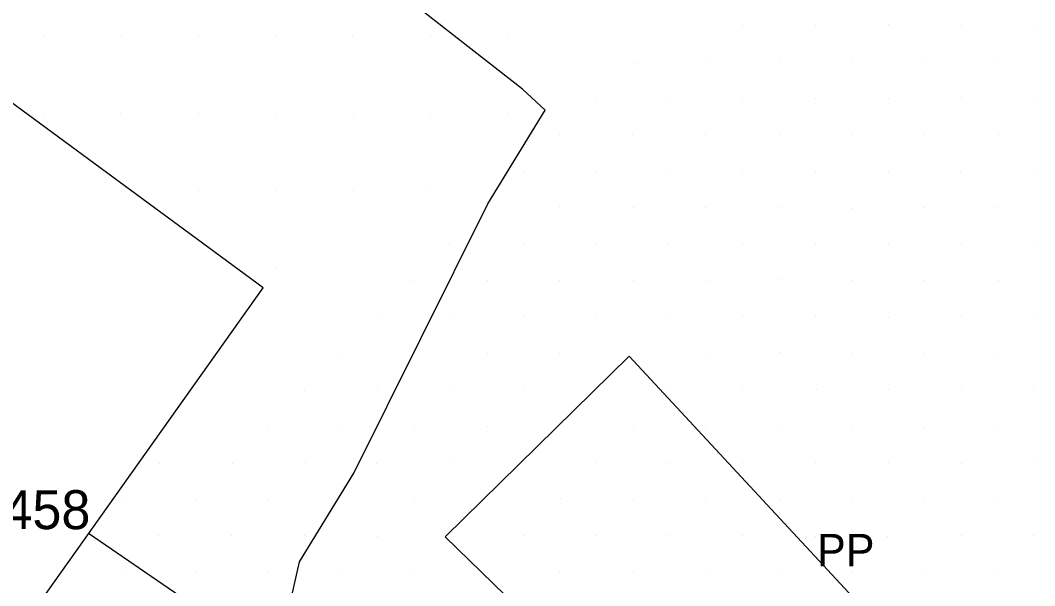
# Model space of a CAD drawing. Extents: x 1602514 to 1609837, y 863887 to 871157.
# Drawn here: x 1605194.3 to 1605391, y 866946.5 to 867056.2 of the extents above; entities that cross this region are included whole.
import ezdxf

# ---------------------------------------------------------------- set-up
doc = ezdxf.new("R2010")
doc.units = 0
for name, color, linetype in [('Survey-Buildings', 7, 'Continuous'), ('Survey-Edge of pavement', 7, 'Continuous'), ('Survey-Entrances', 7, 'Continuous'), ('Survey-Fences', 7, 'Continuous'), ('Survey-Spot dirt', 7, 'Continuous'), ('Survey-Text-Elevation', 7, 'Continuous'), ('Utility-Pole', 7, 'Continuous')]:
    doc.layers.add(name, color=color, linetype=linetype)

msp = doc.modelspace()

# ---------------------------------------------------------------- linework, layer by layer
at = {"layer": 'Survey-Buildings'}
msp.add_lwpolyline([(1605190.06, 866932.05), (1605241.42, 867004.29), (1605170.03, 867056.81), (1605155.81, 867037.05), (1605154.06, 867034.61), (1605138.78, 867044.23), (1605166.94, 867086.69), (1605169.84, 867084.69), (1605184.21, 867105.16), (1605132.01, 867142.68), (1605116.66, 867120.43), (1605129.33, 867112.32), (1605120.65, 867099.05), (1605101.98, 867070.67), (1605103.93, 867068.47), (1605097.48, 867060.65), (1605146.75, 867024.45), (1605117.85, 866984.27), (1605136.88, 866970.51)], dxfattribs=at)
msp.add_lwpolyline([(1605190.06, 866932.05), (1605241.42, 867004.29), (1605170.03, 867056.81), (1605155.81, 867037.05), (1605154.06, 867034.61), (1605138.78, 867044.23), (1605166.94, 867086.69), (1605169.84, 867084.69), (1605184.21, 867105.16), (1605132.01, 867142.68), (1605116.66, 867120.43), (1605129.33, 867112.32), (1605120.65, 867099.05), (1605101.98, 867070.67), (1605103.93, 867068.47), (1605097.48, 867060.65), (1605146.75, 867024.45), (1605117.85, 866984.27), (1605136.88, 866970.51)], dxfattribs=at)
at = {"layer": 'Survey-Edge of pavement'}
msp.add_lwpolyline([(1605073.3, 866946.51), (1605034.83, 866891.76), (1605147.19, 866811.71), (1605195.19, 866879.11), (1605236.38, 866936.87), (1605207.52, 866956.61)], dxfattribs=at)
msp.add_lwpolyline([(1605073.3, 866946.51), (1605034.83, 866891.76), (1605147.19, 866811.71), (1605195.19, 866879.11), (1605236.38, 866936.87), (1605207.52, 866956.61)], dxfattribs=at)
at = {"layer": 'Survey-Entrances'}
for points in [[(1605291.69, 867042.8), (1605245.98, 867078.59), (1605219.04, 867104.4), (1605203.54, 867111.71), (1605201.31, 867118.34)], [(1605291.69, 867042.8), (1605245.98, 867078.59), (1605219.04, 867104.4), (1605203.54, 867111.71), (1605201.31, 867118.34)], [(1605244.46, 866933.37), (1605248.44, 866951.15), (1605258.96, 866968.37), (1605284.98, 867020.57), (1605296.07, 867038.78), (1605291.69, 867042.8)], [(1605244.46, 866933.37), (1605248.44, 866951.15), (1605258.96, 866968.37), (1605284.98, 867020.57), (1605296.07, 867038.78), (1605291.69, 867042.8)]]:
    msp.add_lwpolyline(points, dxfattribs=at)
at = {"layer": 'Survey-Fences'}
msp.add_lwpolyline([(1605276.69, 866955.98), (1605312.32, 866991.05), (1605363.36, 866936.1), (1605330.31, 866903.81)], close=True, dxfattribs=at)
msp.add_lwpolyline([(1605276.69, 866955.98), (1605312.32, 866991.05), (1605363.36, 866936.1), (1605330.31, 866903.81)], close=True, dxfattribs=at)
at = {"layer": 'Survey-Spot dirt'}
for p, q in [((1605362.66, 867055.34), (1605362.66, 867055.34)), ((1605362.66, 867055.34), (1605362.66, 867055.34)), ((1605334.23, 867055.22), (1605334.23, 867055.22)), ((1605334.23, 867055.22), (1605334.23, 867055.22)), ((1605348.41, 867055.12), (1605348.41, 867055.12)), ((1605348.41, 867055.12), (1605348.41, 867055.12)), ((1605376.74, 867055.15), (1605376.74, 867055.15)), ((1605376.74, 867055.15), (1605376.74, 867055.15)), ((1605390.85, 867055.23), (1605390.85, 867055.23)), ((1605390.85, 867055.23), (1605390.85, 867055.23)), ((1605198.88, 867053.12), (1605198.88, 867053.12)), ((1605198.88, 867053.12), (1605198.88, 867053.12)), ((1605213.9, 867053.06), (1605213.9, 867053.06)), ((1605213.9, 867053.06), (1605213.9, 867053.06)), ((1605228.95, 867053.03), (1605228.95, 867053.03)), ((1605228.95, 867053.03), (1605228.95, 867053.03)), ((1605243.8, 867053.08), (1605243.8, 867053.08)), ((1605243.8, 867053.08), (1605243.8, 867053.08)), ((1605258.8, 867053.03), (1605258.8, 867053.03)), ((1605258.8, 867053.03), (1605258.8, 867053.03)), ((1605273.88, 867053.03), (1605273.88, 867053.03)), ((1605273.88, 867053.03), (1605273.88, 867053.03)), ((1605288.98, 867052.83), (1605288.98, 867052.83)), ((1605288.98, 867052.83), (1605288.98, 867052.83)), ((1605313.3, 867047.8), (1605313.3, 867047.8)), ((1605313.3, 867047.8), (1605313.3, 867047.8)), ((1605327.26, 867048.04), (1605327.26, 867048.04)), ((1605327.26, 867048.04), (1605327.26, 867048.04)), ((1605341.43, 867048.16), (1605341.43, 867048.16)), ((1605341.43, 867048.16), (1605341.43, 867048.16)), ((1605355.55, 867048.12), (1605355.55, 867048.12)), ((1605355.55, 867048.12), (1605355.55, 867048.12)), ((1605369.74, 867048.04), (1605369.74, 867048.04)), ((1605369.74, 867048.04), (1605369.74, 867048.04)), ((1605383.81, 867048.19), (1605383.81, 867048.19)), ((1605383.81, 867048.19), (1605383.81, 867048.19)), ((1605306.04, 867041.1), (1605306.04, 867041.1)), ((1605306.04, 867041.1), (1605306.04, 867041.1)), ((1605320.17, 867041.04), (1605320.17, 867041.04)), ((1605320.17, 867041.04), (1605320.17, 867041.04)), ((1605334.28, 867040.99), (1605334.28, 867040.99)), ((1605334.28, 867040.99), (1605334.28, 867040.99)), ((1605348.38, 867041.04), (1605348.38, 867041.04)), ((1605348.38, 867041.04), (1605348.38, 867041.04)), ((1605362.64, 867041.07), (1605362.64, 867041.07)), ((1605362.64, 867041.07), (1605362.64, 867041.07)), ((1605376.73, 867041.14), (1605376.73, 867041.14)), ((1605376.73, 867041.14), (1605376.73, 867041.14)), ((1605390.95, 867040.91), (1605390.95, 867040.91)), ((1605390.95, 867040.91), (1605390.95, 867040.91)), ((1605199.02, 867037.9), (1605199.02, 867037.9)), ((1605199.02, 867037.9), (1605199.02, 867037.9)), ((1605213.79, 867038.08), (1605213.79, 867038.08)), ((1605213.79, 867038.08), (1605213.79, 867038.08)), ((1605228.86, 867038.07), (1605228.86, 867038.07)), ((1605228.86, 867038.07), (1605228.86, 867038.07)), ((1605243.89, 867038), (1605243.89, 867038)), ((1605243.89, 867038), (1605243.89, 867038)), ((1605258.93, 867037.97), (1605258.93, 867037.97)), ((1605258.93, 867037.97), (1605258.93, 867037.97)), ((1605273.9, 867037.99), (1605273.9, 867037.99)), ((1605273.9, 867037.99), (1605273.9, 867037.99)), ((1605288.84, 867038.05), (1605288.84, 867038.05)), ((1605288.84, 867038.05), (1605288.84, 867038.05)), ((1605298.84, 867033.98), (1605298.84, 867033.98)), ((1605298.84, 867033.98), (1605298.84, 867033.98)), ((1605312.99, 867034.05), (1605312.99, 867034.05)), ((1605312.99, 867034.05), (1605312.99, 867034.05)), ((1605327.18, 867033.98), (1605327.18, 867033.98)), ((1605327.18, 867033.98), (1605327.18, 867033.98)), ((1605341.43, 867034.06), (1605341.43, 867034.06)), ((1605341.43, 867034.06), (1605341.43, 867034.06)), ((1605355.58, 867033.99), (1605355.58, 867033.99)), ((1605355.58, 867033.99), (1605355.58, 867033.99)), ((1605369.67, 867033.97), (1605369.67, 867033.97)), ((1605369.67, 867033.97), (1605369.67, 867033.97)), ((1605383.86, 867034.06), (1605383.86, 867034.06)), ((1605383.86, 867034.06), (1605383.86, 867034.06)), ((1605291.89, 867026.86), (1605291.89, 867026.86)), ((1605291.89, 867026.86), (1605291.89, 867026.86)), ((1605305.92, 867026.89), (1605305.92, 867026.89)), ((1605305.92, 867026.89), (1605305.92, 867026.89)), ((1605320.18, 867026.81), (1605320.18, 867026.81)), ((1605320.18, 867026.81), (1605320.18, 867026.81)), ((1605334.36, 867026.97), (1605334.36, 867026.97)), ((1605334.36, 867026.97), (1605334.36, 867026.97)), ((1605348.51, 867026.93), (1605348.51, 867026.93)), ((1605348.51, 867026.93), (1605348.51, 867026.93)), ((1605362.65, 867026.86), (1605362.65, 867026.86)), ((1605362.65, 867026.86), (1605362.65, 867026.86)), ((1605376.65, 867026.89), (1605376.65, 867026.89)), ((1605376.65, 867026.89), (1605376.65, 867026.89)), ((1605390.88, 867026.87), (1605390.88, 867026.87)), ((1605390.88, 867026.87), (1605390.88, 867026.87)), ((1605214, 867023.17), (1605214, 867023.17)), ((1605214, 867023.17), (1605214, 867023.17)), ((1605228.94, 867023.1), (1605228.94, 867023.1)), ((1605228.94, 867023.1), (1605228.94, 867023.1)), ((1605243.78, 867023.08), (1605243.78, 867023.08)), ((1605243.78, 867023.08), (1605243.78, 867023.08)), ((1605259, 867023.11), (1605259, 867023.11)), ((1605259, 867023.11), (1605259, 867023.11)), ((1605273.66, 867023.15), (1605273.66, 867023.15)), ((1605273.66, 867023.15), (1605273.66, 867023.15)), ((1605298.82, 867020.05), (1605298.82, 867020.05)), ((1605298.82, 867020.05), (1605298.82, 867020.05)), ((1605313.19, 867019.85), (1605313.19, 867019.85)), ((1605313.19, 867019.85), (1605313.19, 867019.85)), ((1605327.22, 867019.94), (1605327.22, 867019.94)), ((1605327.22, 867019.94), (1605327.22, 867019.94)), ((1605341.3, 867019.84), (1605341.3, 867019.84)), ((1605341.3, 867019.84), (1605341.3, 867019.84)), ((1605369.62, 867019.87), (1605369.62, 867019.87)), ((1605369.62, 867019.87), (1605369.62, 867019.87)), ((1605383.73, 867019.87), (1605383.73, 867019.87)), ((1605383.73, 867019.87), (1605383.73, 867019.87)), ((1605355.46, 867019.75), (1605355.46, 867019.75)), ((1605355.46, 867019.75), (1605355.46, 867019.75)), ((1605277.61, 867012.75), (1605277.61, 867012.75)), ((1605277.61, 867012.75), (1605277.61, 867012.75)), ((1605291.93, 867012.74), (1605291.93, 867012.74)), ((1605291.93, 867012.74), (1605291.93, 867012.74)), ((1605306.04, 867012.84), (1605306.04, 867012.84)), ((1605306.04, 867012.84), (1605306.04, 867012.84)), ((1605320.01, 867012.81), (1605320.01, 867012.81)), ((1605320.01, 867012.81), (1605320.01, 867012.81)), ((1605334.3, 867012.77), (1605334.3, 867012.77)), ((1605334.3, 867012.77), (1605334.3, 867012.77)), ((1605348.57, 867012.77), (1605348.57, 867012.77)), ((1605348.57, 867012.77), (1605348.57, 867012.77)), ((1605362.62, 867012.81), (1605362.62, 867012.81)), ((1605362.62, 867012.81), (1605362.62, 867012.81)), ((1605376.7, 867012.83), (1605376.7, 867012.83)), ((1605376.7, 867012.83), (1605376.7, 867012.83)), ((1605390.97, 867012.76), (1605390.97, 867012.76)), ((1605390.97, 867012.76), (1605390.97, 867012.76)), ((1605243.86, 867008.03), (1605243.86, 867008.03)), ((1605243.86, 867008.03), (1605243.86, 867008.03)), ((1605270.58, 867005.74), (1605270.58, 867005.74)), ((1605270.58, 867005.74), (1605270.58, 867005.74)), ((1605284.85, 867005.73), (1605284.85, 867005.73)), ((1605284.85, 867005.73), (1605284.85, 867005.73)), ((1605298.9, 867005.69), (1605298.9, 867005.69)), ((1605298.9, 867005.69), (1605298.9, 867005.69)), ((1605313.19, 867005.66), (1605313.19, 867005.66)), ((1605313.19, 867005.66), (1605313.19, 867005.66)), ((1605327.34, 867005.7), (1605327.34, 867005.7)), ((1605327.34, 867005.7), (1605327.34, 867005.7)), ((1605341.23, 867005.86), (1605341.23, 867005.86)), ((1605341.23, 867005.86), (1605341.23, 867005.86)), ((1605355.49, 867005.75), (1605355.49, 867005.75)), ((1605355.49, 867005.75), (1605355.49, 867005.75)), ((1605369.58, 867005.74), (1605369.58, 867005.74)), ((1605369.58, 867005.74), (1605369.58, 867005.74)), ((1605383.88, 867005.63), (1605383.88, 867005.63)), ((1605383.88, 867005.63), (1605383.88, 867005.63)), ((1605263.71, 866998.6), (1605263.71, 866998.6)), ((1605263.71, 866998.6), (1605263.71, 866998.6)), ((1605277.7, 866998.53), (1605277.7, 866998.53)), ((1605277.7, 866998.53), (1605277.7, 866998.53)), ((1605291.8, 866998.67), (1605291.8, 866998.67)), ((1605291.8, 866998.67), (1605291.8, 866998.67)), ((1605305.92, 866998.61), (1605305.92, 866998.61)), ((1605305.92, 866998.61), (1605305.92, 866998.61)), ((1605320.22, 866998.63), (1605320.22, 866998.63)), ((1605320.22, 866998.63), (1605320.22, 866998.63)), ((1605334.26, 866998.78), (1605334.26, 866998.78)), ((1605334.26, 866998.78), (1605334.26, 866998.78)), ((1605348.55, 866998.69), (1605348.55, 866998.69)), ((1605348.55, 866998.69), (1605348.55, 866998.69)), ((1605362.69, 866998.58), (1605362.69, 866998.58)), ((1605362.69, 866998.58), (1605362.69, 866998.58)), ((1605376.76, 866998.67), (1605376.76, 866998.67)), ((1605376.76, 866998.67), (1605376.76, 866998.67)), ((1605390.89, 866998.48), (1605390.89, 866998.48)), ((1605390.89, 866998.48), (1605390.89, 866998.48)), ((1605256.53, 866991.54), (1605256.53, 866991.54)), ((1605256.53, 866991.54), (1605256.53, 866991.54)), ((1605270.63, 866991.61), (1605270.63, 866991.61)), ((1605270.63, 866991.61), (1605270.63, 866991.61)), ((1605284.85, 866991.65), (1605284.85, 866991.65)), ((1605284.85, 866991.65), (1605284.85, 866991.65)), ((1605298.89, 866991.49), (1605298.89, 866991.49)), ((1605298.89, 866991.49), (1605298.89, 866991.49)), ((1605327.3, 866991.46), (1605327.3, 866991.46)), ((1605327.3, 866991.46), (1605327.3, 866991.46)), ((1605341.41, 866991.69), (1605341.41, 866991.69)), ((1605341.41, 866991.69), (1605341.41, 866991.69)), ((1605355.59, 866991.54), (1605355.59, 866991.54)), ((1605355.59, 866991.54), (1605355.59, 866991.54)), ((1605369.61, 866991.56), (1605369.61, 866991.56)), ((1605369.61, 866991.56), (1605369.61, 866991.56)), ((1605383.79, 866991.57), (1605383.79, 866991.57)), ((1605383.79, 866991.57), (1605383.79, 866991.57)), ((1605249.5, 866984.45), (1605249.5, 866984.45)), ((1605249.5, 866984.45), (1605249.5, 866984.45)), ((1605263.62, 866984.57), (1605263.62, 866984.57)), ((1605263.62, 866984.57), (1605263.62, 866984.57)), ((1605277.65, 866984.53), (1605277.65, 866984.53)), ((1605277.65, 866984.53), (1605277.65, 866984.53)), ((1605291.93, 866984.55), (1605291.93, 866984.55)), ((1605291.93, 866984.55), (1605291.93, 866984.55)), ((1605320.15, 866984.53), (1605320.15, 866984.53)), ((1605320.15, 866984.53), (1605320.15, 866984.53)), ((1605334.24, 866984.59), (1605334.24, 866984.59)), ((1605334.24, 866984.59), (1605334.24, 866984.59)), ((1605348.67, 866984.55), (1605348.67, 866984.55)), ((1605348.67, 866984.55), (1605348.67, 866984.55)), ((1605362.57, 866984.49), (1605362.57, 866984.49)), ((1605362.57, 866984.49), (1605362.57, 866984.49)), ((1605376.74, 866984.58), (1605376.74, 866984.58)), ((1605376.74, 866984.58), (1605376.74, 866984.58)), ((1605390.81, 866984.53), (1605390.81, 866984.53)), ((1605390.81, 866984.53), (1605390.81, 866984.53)), ((1605242.29, 866977.37), (1605242.29, 866977.37)), ((1605242.29, 866977.37), (1605242.29, 866977.37)), ((1605256.52, 866977.46), (1605256.52, 866977.46)), ((1605256.52, 866977.46), (1605256.52, 866977.46)), ((1605270.72, 866977.43), (1605270.72, 866977.43)), ((1605270.72, 866977.43), (1605270.72, 866977.43)), ((1605284.8, 866977.4), (1605284.8, 866977.4)), ((1605284.8, 866977.4), (1605284.8, 866977.4)), ((1605313.25, 866977.42), (1605313.25, 866977.42)), ((1605313.25, 866977.42), (1605313.25, 866977.42)), ((1605327.21, 866977.36), (1605327.21, 866977.36)), ((1605327.21, 866977.36), (1605327.21, 866977.36)), ((1605341.32, 866977.44), (1605341.32, 866977.44)), ((1605341.32, 866977.44), (1605341.32, 866977.44)), ((1605355.57, 866977.41), (1605355.57, 866977.41)), ((1605355.57, 866977.41), (1605355.57, 866977.41)), ((1605369.66, 866977.27), (1605369.66, 866977.27)), ((1605369.66, 866977.27), (1605369.66, 866977.27)), ((1605383.75, 866977.33), (1605383.75, 866977.33)), ((1605383.75, 866977.33), (1605383.75, 866977.33)), ((1605221.39, 866970.21), (1605221.39, 866970.21)), ((1605221.39, 866970.21), (1605221.39, 866970.21)), ((1605235.48, 866970.28), (1605235.48, 866970.28)), ((1605235.48, 866970.28), (1605235.48, 866970.28)), ((1605249.51, 866970.33), (1605249.51, 866970.33)), ((1605249.51, 866970.33), (1605249.51, 866970.33)), ((1605263.36, 866970.24), (1605263.36, 866970.24)), ((1605263.36, 866970.24), (1605263.36, 866970.24)), ((1605277.71, 866970.33), (1605277.71, 866970.33)), ((1605277.71, 866970.33), (1605277.71, 866970.33)), ((1605305.94, 866970.41), (1605305.94, 866970.41)), ((1605305.94, 866970.41), (1605305.94, 866970.41)), ((1605320.19, 866970.26), (1605320.19, 866970.26)), ((1605320.19, 866970.26), (1605320.19, 866970.26)), ((1605334.3, 866970.33), (1605334.3, 866970.33)), ((1605334.3, 866970.33), (1605334.3, 866970.33)), ((1605348.39, 866970.49), (1605348.39, 866970.49)), ((1605348.39, 866970.49), (1605348.39, 866970.49)), ((1605362.59, 866970.35), (1605362.59, 866970.35)), ((1605362.59, 866970.35), (1605362.59, 866970.35)), ((1605376.74, 866970.28), (1605376.74, 866970.28)), ((1605376.74, 866970.28), (1605376.74, 866970.28)), ((1605390.9, 866970.46), (1605390.9, 866970.46)), ((1605390.9, 866970.46), (1605390.9, 866970.46)), ((1605214.22, 866963.37), (1605214.22, 866963.37)), ((1605214.22, 866963.37), (1605214.22, 866963.37)), ((1605228.25, 866963.3), (1605228.25, 866963.3)), ((1605228.25, 866963.3), (1605228.25, 866963.3)), ((1605242.39, 866963.31), (1605242.39, 866963.31)), ((1605242.39, 866963.31), (1605242.39, 866963.31)), ((1605270.74, 866963.41), (1605270.74, 866963.41)), ((1605270.74, 866963.41), (1605270.74, 866963.41)), ((1605298.96, 866963.36), (1605298.96, 866963.36)), ((1605298.96, 866963.36), (1605298.96, 866963.36)), ((1605313.12, 866963.22), (1605313.12, 866963.22)), ((1605313.12, 866963.22), (1605313.12, 866963.22)), ((1605327.22, 866963.33), (1605327.22, 866963.33)), ((1605327.22, 866963.33), (1605327.22, 866963.33)), ((1605341.42, 866963.28), (1605341.42, 866963.28)), ((1605341.42, 866963.28), (1605341.42, 866963.28)), ((1605355.49, 866963.33), (1605355.49, 866963.33)), ((1605355.49, 866963.33), (1605355.49, 866963.33)), ((1605369.56, 866963.33), (1605369.56, 866963.33)), ((1605369.56, 866963.33), (1605369.56, 866963.33)), ((1605383.79, 866963.24), (1605383.79, 866963.24)), ((1605383.79, 866963.24), (1605383.79, 866963.24)), ((1605221.14, 866956.32), (1605221.14, 866956.32)), ((1605221.14, 866956.32), (1605221.14, 866956.32)), ((1605235.34, 866956.2), (1605235.34, 866956.2)), ((1605235.34, 866956.2), (1605235.34, 866956.2)), ((1605249.49, 866956.19), (1605249.49, 866956.19)), ((1605249.49, 866956.19), (1605249.49, 866956.19)), ((1605263.6, 866956.08), (1605263.6, 866956.08)), ((1605263.6, 866956.08), (1605263.6, 866956.08)), ((1605291.91, 866956.23), (1605291.91, 866956.23)), ((1605291.91, 866956.23), (1605291.91, 866956.23)), ((1605306.01, 866956.24), (1605306.01, 866956.24)), ((1605306.01, 866956.24), (1605306.01, 866956.24)), ((1605320.15, 866956.23), (1605320.15, 866956.23)), ((1605320.15, 866956.23), (1605320.15, 866956.23)), ((1605334.29, 866956.21), (1605334.29, 866956.21)), ((1605334.29, 866956.21), (1605334.29, 866956.21)), ((1605348.42, 866956.14), (1605348.42, 866956.14)), ((1605348.42, 866956.14), (1605348.42, 866956.14)), ((1605362.5, 866956.09), (1605362.5, 866956.09)), ((1605362.5, 866956.09), (1605362.5, 866956.09)), ((1605376.78, 866956.24), (1605376.78, 866956.24)), ((1605376.78, 866956.24), (1605376.78, 866956.24)), ((1605390.74, 866956.2), (1605390.74, 866956.2)), ((1605390.74, 866956.2), (1605390.74, 866956.2)), ((1605214.15, 866949.14), (1605214.15, 866949.14)), ((1605214.15, 866949.14), (1605214.15, 866949.14)), ((1605228.24, 866949.14), (1605228.24, 866949.14)), ((1605228.24, 866949.14), (1605228.24, 866949.14)), ((1605256.57, 866949.15), (1605256.57, 866949.15)), ((1605256.57, 866949.15), (1605256.57, 866949.15)), ((1605270.63, 866949.07), (1605270.63, 866949.07)), ((1605270.63, 866949.07), (1605270.63, 866949.07)), ((1605284.89, 866949.1), (1605284.89, 866949.1)), ((1605284.89, 866949.1), (1605284.89, 866949.1)), ((1605298.93, 866949.12), (1605298.93, 866949.12)), ((1605298.93, 866949.12), (1605298.93, 866949.12)), ((1605313.19, 866949.16), (1605313.19, 866949.16)), ((1605313.19, 866949.16), (1605313.19, 866949.16)), ((1605341.34, 866949.08), (1605341.34, 866949.08)), ((1605341.34, 866949.08), (1605341.34, 866949.08)), ((1605355.55, 866949.2), (1605355.55, 866949.2)), ((1605355.55, 866949.2), (1605355.55, 866949.2)), ((1605369.77, 866949.23), (1605369.77, 866949.23)), ((1605369.77, 866949.23), (1605369.77, 866949.23)), ((1605383.74, 866949.21), (1605383.74, 866949.21)), ((1605383.74, 866949.21), (1605383.74, 866949.21)), ((1605242.44, 866949.01), (1605242.44, 866949.01)), ((1605242.44, 866949.01), (1605242.44, 866949.01)), ((1605327.34, 866949.03), (1605327.34, 866949.03)), ((1605327.34, 866949.03), (1605327.34, 866949.03))]:
    msp.add_line(p, q, dxfattribs=at)

# ---------------------------------------------------------------- texts
at = {"layer": 'Survey-Text-Elevation'}
msp.add_text('814.6458', height=7.56, dxfattribs=at).set_placement((1605165.74, 866957.48))
msp.add_text('814.6458', height=7.56, dxfattribs=at).set_placement((1605165.74, 866957.48))
at = {"layer": 'Utility-Pole'}
msp.add_text('PP', height=6.251, dxfattribs=at).set_placement((1605348.76, 866950.29))
msp.add_text('PP', height=6.251, dxfattribs=at).set_placement((1605348.76, 866950.29))

doc.saveas('drawing.dxf')
